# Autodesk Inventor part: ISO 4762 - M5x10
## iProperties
Author: Philippe
Created: 2001-12
Part Number: ISO 4762 - M5x10
Material: Par défaut
Catalog Web Link: file:///C:/Program Files/Autodesk/Inventor 5/Content/Iso/index.htm?doNavigateId=932883F9-F3A7-4770-8571-ED868C9DA26C|BD6CAEC25FC54C5988A91C985F78BFEA|true
Description: Vis cylindrique à six pans creux
Document SubType Name: Standard Catalog Part
Standard: ISO 4762 - M5x10
Designer: Philippe
CLASSIFICATION: 31161501 un/spsc
MANUFACTURER: ISO Système de normes
Control State: 0
Master: False
Checked Out: False
PropertySet Name: Design Tracking Control
Shininess: 20.0
Angle Display Precision: 2
Document Length Units: 11269
Document Angle Units: 11283
Document Time Units: 11279
Document Mass Units: 11290
Document Length Units Precision: 3
Document Angle Units Precision: 2
Compacted: False
PropertySet Name: _Private Model Information
Density: 0.0
Volumn: 0.0
Area: 0.0
PropertySet Name: Model Information
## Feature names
1. Base1
